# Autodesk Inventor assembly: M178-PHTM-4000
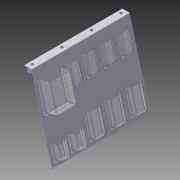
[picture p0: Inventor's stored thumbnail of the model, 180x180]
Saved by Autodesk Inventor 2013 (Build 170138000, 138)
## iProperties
Created: 2004-11
Part Number: M178-PHTM-4000
Document SubType Name: Assembly
Designer: Autodesk, Inc.
Manufacturer: Standard
Standards Organization: Custom
Mass: 1631.06 g
Surface Area: 9213.9 cm^2
Volume: 761.26 cm^3
Density: 2.14258 g/cm^3
CAGE: 1LJX3
Dept. ID: Product Design
Description #2: ---
Finish #1: ---
Finish #2: ---
Material ID: ---
Project Number: ---
Author: Autodesk, Inc.
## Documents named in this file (7)
- Z:\_DATEN\Test Station\Components\M178-4000 Phantom.iam
- Z:\_DATEN\Test Station\Components\M178-4000.iam
- Z:\_DATEN\Test Station\Components\24-112-8.ipt
- Z:\_DATEN\Test Station\Components\24-116-8.ipt
- Z:\_DATEN\Test Station\Components\20-058.ipt
- C:\Users\kelleyb.ADS\Desktop\Samples MIGRATED 2009 224 RTM_1\Standard Parts\Test Station Content\Fastners\2X-YYY-ZZ IPS Screws.ipt
- C:\Users\kelleyb.ADS\Desktop\Samples MIGRATED 2009 224 RTM_1\Standard Parts\Test Station Content\Fastners\20-XXX TSlot Nuts.ipt
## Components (13 placed, 4 different names)
1. M178-4000:1 [sub-assembly] — Insert:1, Mate:3, Angle:1
2. 24-112-8:1 — Insert:1, Mate:1
3. 20-058:1 — Mate:1, Mate:3, Angle:1
4. 24-112-8:2
5. 20-058:3
6. 24-112-8:3
7. 20-058:4
8. 24-112-8:4
9. 20-058:5
10. 20-058:2 — Mate:2
11. 24-116-8:5 — Mate:2
12. 20-058:6
13. 24-116-8:6
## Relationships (5: Mate 3, Insert 1, Angle 1)
- Insert:1: M178-4000:1 ↔ 24-112-8:1
- Mate:1: 24-112-8:1 ↔ 20-058:1
- Mate:2: 20-058:2 ↔ 24-116-8:5
- Mate:3: M178-4000:1 ↔ 20-058:1
- Angle:1: M178-4000:1 ↔ 20-058:1
